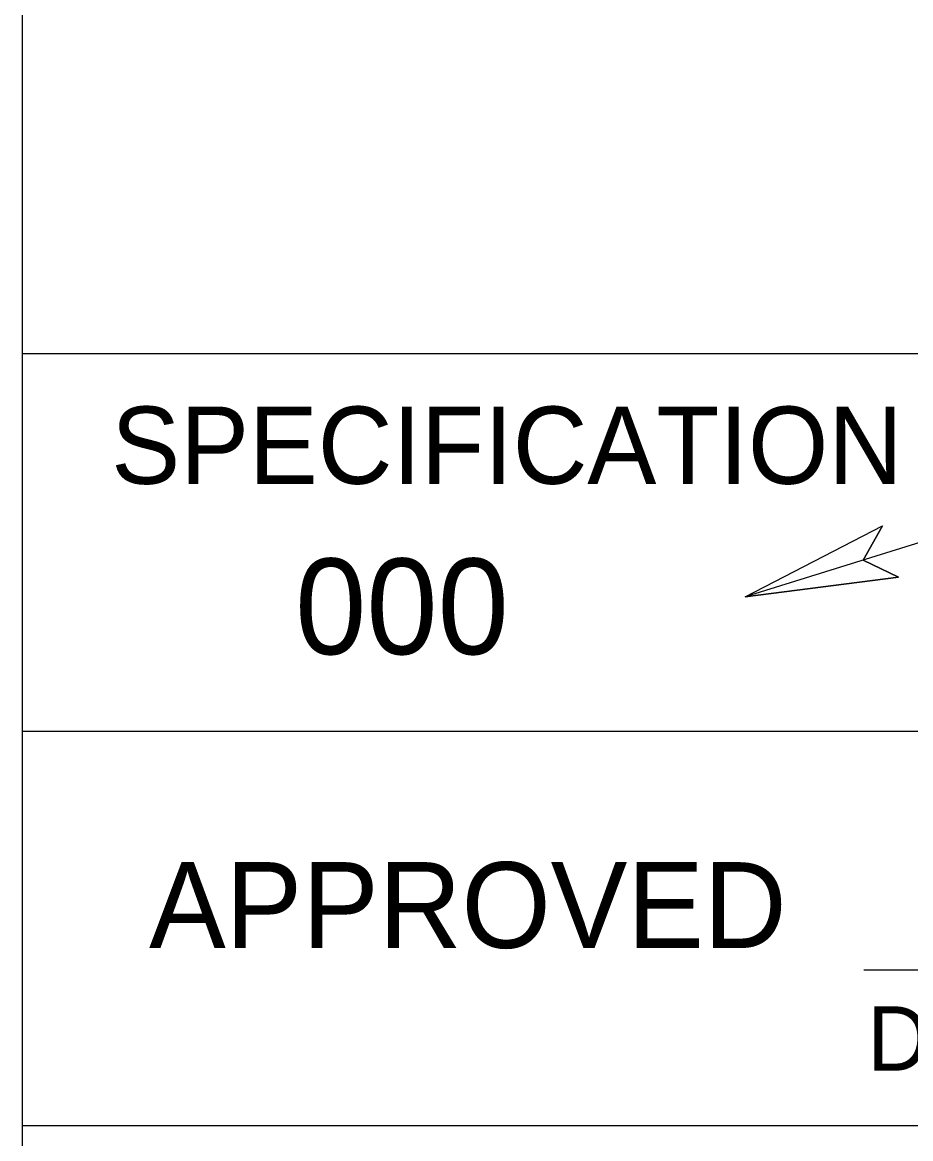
# Model space of a CAD drawing. Extents: x -0.5 to 21.6, y 4.3 to 17.8.
# Drawn here: x 0.394 to 1.229, y 6.651 to 7.7 of the extents above; entities that cross this region are included whole.
import ezdxf

# ---------------------------------------------------------------- set-up
doc = ezdxf.new("R2010")
doc.units = 0
for name, color, linetype in [('DETL-DIMS', 7, 'Continuous'), ('DETL-LINE', 7, 'Continuous'), ('DETL-NOTE', 7, 'Continuous'), ('TTLB-TEXT', 7, 'Continuous'), ('USER-BORD', 7, 'Continuous')]:
    doc.layers.add(name, color=color, linetype=linetype)

msp = doc.modelspace()

# ---------------------------------------------------------------- linework, layer by layer
at = {"layer": 'DETL-DIMS'}
for p, q in [((2.6792, 7.6599), (1.0734, 7.16)), ((1.0734, 7.16), (1.2024, 7.2266)), ((1.1842, 7.1945), (1.2024, 7.2266)), ((1.2174, 7.1784), (1.1842, 7.1945)), ((1.0734, 7.16), (1.2174, 7.1784))]:
    msp.add_line(p, q, dxfattribs=at)
msp.add_lwpolyline([(1.2174, 7.1784), (1.0734, 7.16), (1.2024, 7.2266), (1.1842, 7.1945)], close=True, dxfattribs=at)
at = {"layer": 'DETL-LINE'}
msp.add_lwpolyline([(0.3943, 14.1527), (0.3943, 16.2906), (7.7685, 16.2906), (7.7685, 5.9375), (0.3943, 5.9375), (0.3943, 13.6862)], dxfattribs=at)
at = {"layer": 'DETL-NOTE'}
msp.add_line((1.1851, 6.8093), (3.192, 6.8093), dxfattribs=at)
at = {"layer": 'TTLB-TEXT'}
for p, q in [((0.3943, 7.3883), (0.3943, 16.2906)), ((0.3943, 5.9375), (0.3943, 7.3883)), ((7.7685, 7.3883), (0.3943, 7.3883)), ((0.3943, 7.0336), (3.2956, 7.0336)), ((0.3943, 6.6629), (1.2405, 6.6629))]:
    msp.add_line(p, q, dxfattribs=at)
msp.add_lwpolyline([(0.3943, 16.2906), (7.7685, 16.2906), (7.7685, 5.9375), (0.3943, 5.9375)], close=True, dxfattribs=at)
at = {"layer": 'USER-BORD'}
for p, q in [((0.3943, 7.3883), (0.3943, 13.6862)), ((0.3943, 5.9375), (0.3943, 7.3883)), ((7.7685, 7.3883), (0.3943, 7.3883)), ((0.3943, 7.0336), (3.2956, 7.0336)), ((0.3943, 6.6629), (1.2405, 6.6629))]:
    msp.add_line(p, q, dxfattribs=at)

# ---------------------------------------------------------------- texts
at = {"layer": 'DETL-NOTE'}
for s, height, p in [('SPECIFICATION', 0.07254, (0.4779, 7.2662)), ('APPROVED', 0.0806, (0.5135, 6.8299))]:
    msp.add_text(s, height=height, dxfattribs=at).set_placement(p)
at = {"layer": 'TTLB-TEXT'}
for s, height, p in [('SPECIFICATION', 0.07254, (0.4778, 7.2661)), ('000', 0.09, (0.6506, 7.1059)), ('APPROVED', 0.0806, (0.5134, 6.8298))]:
    msp.add_text(s, height=height, dxfattribs=at).set_placement(p)
at = {"layer": 'USER-BORD'}
msp.add_text('DEPUTY CHIEF ENGINEER-HIGHWAY DEVELOPMENT', height=0.06045, dxfattribs=at).set_placement((1.1883, 6.7145))

doc.saveas('drawing.dxf')
